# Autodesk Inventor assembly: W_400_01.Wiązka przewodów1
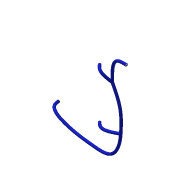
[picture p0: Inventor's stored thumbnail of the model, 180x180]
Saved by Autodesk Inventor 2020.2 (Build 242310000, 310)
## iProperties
Manager: www.cadconsulting.pl
Company: Fabian Stasiak CAD Consulting
ParentFileIdentifier: 5|1|0|0|50|1|0|0|80|0|65|0|84|0|72|0|83|0|59|0|67|0|58|0|92|0|90|0|98|0|105|0|243|0|114|0|32|0|7|1|119|0|105|0|99|0|122|0|101|0|68|1|32|0|65|0|73|0|32|0|50|0|48
Created: 2014-10
Part Number: W_400_01.Wiązka przewodów1
Document SubType Name: Assembly
Designer: F.Stasiak
Catalog Web Link: www.expertbooks.pl
HarnessSettings: <HarnessSettings><Defaults><Segments><Diameter value="0.200 in" fromwires="True"/><Offset value="0.100 in"/><ColorStyle value="Niebieska - farba ścienna - lśnią
Author: F.Stasiak
Subject: Zbiór ćwiczeń. Autodesk Inventor 2020. Kurs Professional
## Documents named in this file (2)
- C:\2020_Kurs_Professional\R2 Wiązki\W_400_01\AIP\przewody i wiązki przewodów\W_400_01.Wiązka przewodów1.iam
- C:\2020_Kurs_Professional\R2 Wiązki\W_400_01\AIP\przewody i wiązki przewodów\W_400_01.Wiązka przewodów1.ipt
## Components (1 placed, 1 different names)
1. Wiązka przewodów1
